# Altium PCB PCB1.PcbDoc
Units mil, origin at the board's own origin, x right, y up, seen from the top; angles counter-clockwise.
Board outline 6000 x 4000 mil, 2 copper layers (Top Layer, Bottom Layer); 112 components, 87 nets, 363 pads, 0 vias.
Unrouted connection lines stored in the file: 248.
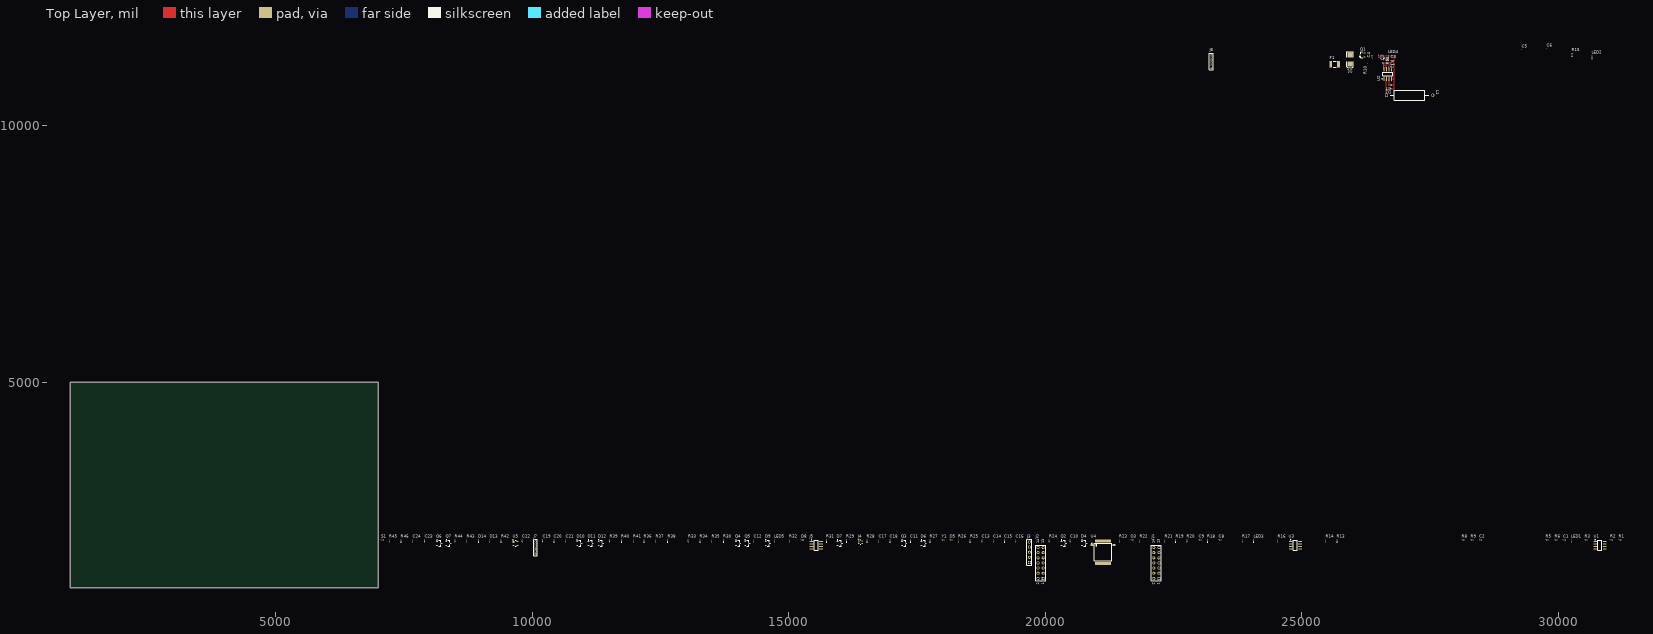
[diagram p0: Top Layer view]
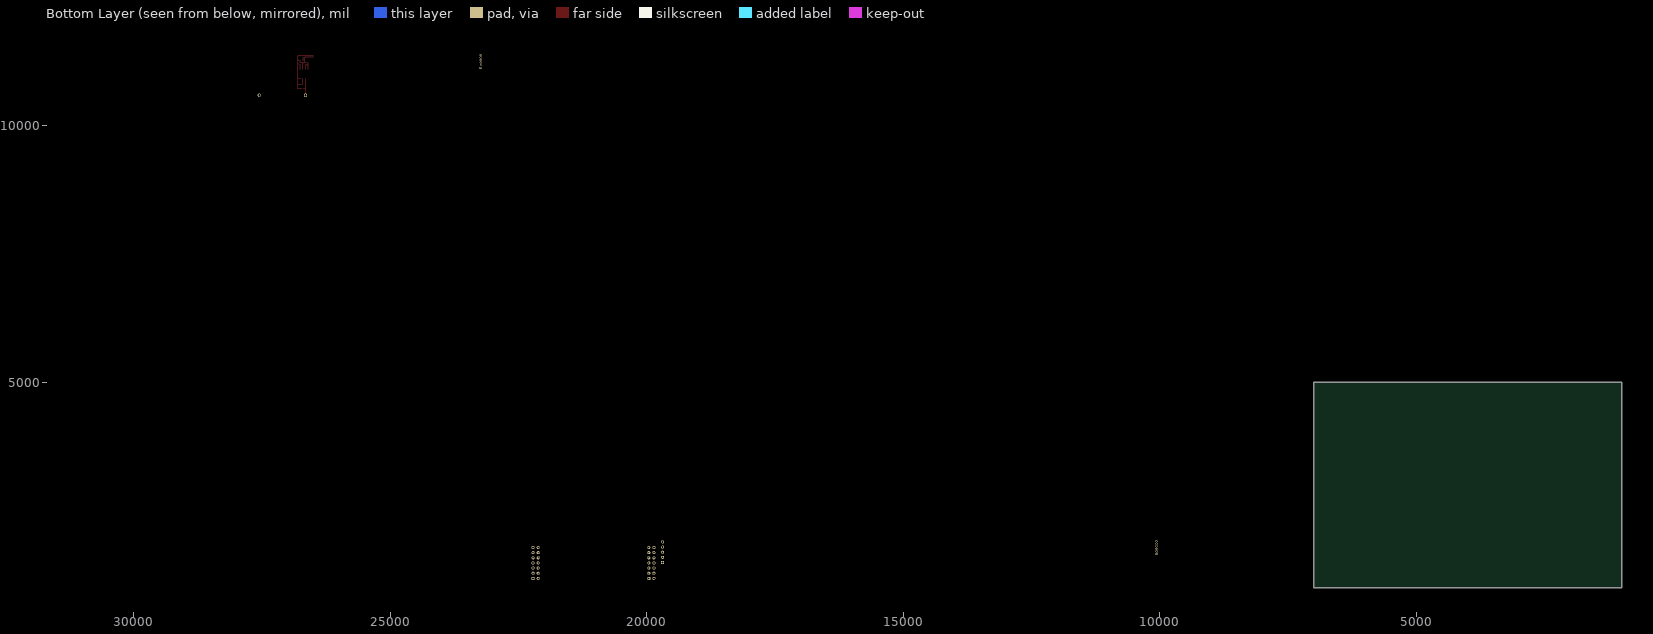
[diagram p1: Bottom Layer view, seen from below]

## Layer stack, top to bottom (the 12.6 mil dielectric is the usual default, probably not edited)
Top Solder: solder mask 0.4, Solder Resist, Dk 3.5
Top Layer: signal copper 1.4
Dielectric 1: dielectric 12.6, FR-4, Dk 4.8
Bottom Layer: signal copper 1.4
Bottom Solder: solder mask 0.4, Solder Resist, Dk 3.5

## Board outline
1000,1000 7000,1000 7000,5000 1000,5000

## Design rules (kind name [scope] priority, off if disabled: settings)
Clearance [All] p1: gap=10 ignorepadtopadclearanceinfootprint=FALSE except(0: Arc-Hole Track-Hole SMDPad-Hole THPad-Hole Via-Hole Fill-Hole Poly-Hole Region-Hole Text-Hole)
PolygonConnect [All] p1: connectstyle=Relief reliefconductorwidth=10 reliefentries=4 polygonreliefangle="90 Angle" airgapwidth=10
RoutingVias [All] p1: holewidth=28 width=50 viastyle="Through Hole" minholewidth=28 minwidth=50 maxholewidth=28 maxwidth=50
SolderMaskExpansion [All] p1: expansion=4
Width [All] p1: maxlimit=10 minlimit=10 preferedwidth=10
30 further rules are at their usual default settings.

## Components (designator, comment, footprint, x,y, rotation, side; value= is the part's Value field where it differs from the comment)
C1 "100n" 0603 30125,1930 r0 top
C2 "4n7" 0603 28490,1930 r0 top value=100n
C3 "4n7" 0603 26500,11351.22 r270 top value=100n
C3 "100n" 0603 26765,11275 r0 top
C4 "10u/16" 0603 26370,11351.22 r90 top value=470u/16
C5 "100u/6V3" 0603 29318.78,11480 r0 top value=470u/16
C6 "100n" 0603 29803.78,11500 r0 top
C7 "100p" 0603 26715,10795 r180 top value=100pF
C8 "100n" 0603 23410,1930 r0 top
C9 "4n7" 0603 23020,1930 r0 top value=100n
C10 "100n" 0603 20485,1915 r90 top
C11 "100n" 0603 17375,1915 r90 top
C12 "100n" 0603 14320,1915 r90 top
C13 "100n" 0603 18765,1915 r90 top
C14 "100n" 0603 18985,1915 r90 top
C15 "100n" 0603 19205,1915 r90 top
C16 "100n" 0603 19425,1915 r90 top
C17 "27p" 0603 16755,1915 r90 top value=100n
C18 "27p" 0603 16975,1915 r90 top value=100n
C19 "100n" 0603 10205,1915 r90 top
C20 "100n" 0603 10425,1915 r90 top
C21 "100n" 0603 10655,1915 r90 top
C22 "100n" 0603 9805,1915 r90 top
C23 "100n" 0603 7905,1915 r90 top
C24 "10n" 0603 7675,1915 r90 top value=100pF
D1 "P6SMB15A" SMB 25940,11291.42 r270 top
D2 "LL5817" 0603 26710,10725 r180 top
D3 "LL4148" 0603 21700,1930 r0 top
D4 "BAT54S" SOT-23_L 20760,1860 r0 top
D5 "LL4148" 0603 18165,1930 r0 top
D6 "BAT54S" SOT-23_L 17630,1860 r0 top
D7 "BAT54S" SOT-23_L 15995,1860 r0 top
D8 "LL4148" 0603 15270,1930 r0 top
D9 "BAT54S" SOT-23_L 14595,1860 r0 top
D10 "BAT54S" SOT-23_L 10920,1860 r0 top
D11 "BAT54S" SOT-23_L 11140,1860 r0 top
D12 "BAT54S" SOT-23_L 11340,1860 r0 top
D13 "LL4148" 0603 9175,1915 r90 top
D14 "LL4448" 0603 8955,1915 r90 top
F1 "Fuse 1" 1812 25640,11200 r0 top
J1 "Header 7X2" HDR2X7 22215,1180 r90 top
J2 "Header 7X2" HDR2X7 19960,1180 r90 top
J3 "ZL201" HDR1X5 19690,1490 r90 top
J4 "MX-43045-0400" SOT-343_L 16400,1885 r0 top
J5 "MX-43045-0800" SO8_L 15535,1825 r0 top
J6 "MX-43045-0600" MHDR1X6 23235,11130 r90 top
J7 "MX-43045-0600" MHDR1x6 10065,1655 r90 top
L1 "DL22-330" AXIAL-0.9 27100,10595 r0 top value=100uH
LED1 "HCL-1904AYL" 0603 30250,1915 r90 top
LED2 "HCL-1903BG4" 0603 30655,11341.22 r90 top
LED3 "HCL-1906BR1" 0603 24060,1915 r90 top
LED4 "HCL-1904AYL" 0603 26690,11350 r90 top
LED5 "HCL-1906BR1" 0603 14720,1915 r90 top
Q1 "BSS138" SOT23_L 26180,11380 r180 top
Q2 "BSS123" SOT-23_L 20360,1860 r0 top
Q3 "BSS123" SOT-23_L 17250,1860 r0 top
Q4 "BSS123" SOT-23_L 14015,1860 r0 top
Q5 "BSS123" SOT-23_L 14195,1860 r0 top
Q6 "BSS123" SOT-23_L 8190,1860 r0 top
Q7 "BSS123" SOT-23_L 8370,1860 r0 top
R1 "CAN0001" 0603 31210,1930 r0 top
R2 "CAN0001" 0603 31040,1930 r0 top
R3 "nc" 0603 30545,1930 r0 top value=1K
R4 "1R" 0603 26613.78,11225 r0 top value=1K
R5 "4k7" 0603 29785,1930 r0 top value=1K
R6 "1k" 0603 29955,1930 r0 top value=1K
R8 "68" 0603 28150,1930 r0 top value=1K
R9 "68" 0603 28320,1930 r0 top value=1K
R10 "1M" 0603 26236.22,11210 r180 top value=1K
R11 "1k2 1%" 0603 26766.22,11195 r180 top value=1K
R12 "4k7" 0603 26675,11275 r0 top value=1K
R13 "CAN0001" 0603 25685,1915 r90 top
R14 "CAN0001" 0603 25465,1915 r90 top
R15 "1k8" 0603 30265,11395 r90 top value=1K
R16 "nc" 0603 24530,1915 r90 top value=1K
R17 "4k7" 0603 23840,1915 r90 top value=1K
R18 "1k" 0603 23160,1915 r90 top value=1K
R19 "68" 0603 22540,1915 r90 top value=1K
R20 "68" 0603 22760,1915 r90 top value=1K
R21 "10k" 0603 22330,1915 r90 top value=1K
R22 "10k" 0603 21840,1915 r90 top value=1K
R23 "1k" 0603 21440,1915 r90 top value=1K
R24 "4k7" 0603 20075,1915 r90 top value=1K
R25 "10k" 0603 18535,1915 r90 top value=1K
R26 "10k" 0603 18305,1915 r90 top value=1K
R27 "1k" 0603 17755,1915 r90 top value=1K
R28 "4k7" 0603 16525,1915 r90 top value=1K
R29 "10k" 0603 16125,1915 r90 top value=1K
R30 "1k8" 0603 13730,1915 r90 top value=1K
R31 "10k" 0603 15735,1915 r90 top value=1K
R32 "1k" 0603 15010,1915 r90 top value=1K
R33 "nc" 0603 13040,1915 r90 top value=1K
R34 "4k7" 0603 13270,1915 r90 top value=1K
R35 "4k7" 0603 13500,1915 r90 top value=1K
R36 "10k" 0603 12180,1915 r90 top value=1K
R37 "10k" 0603 12410,1915 r90 top value=1K
R38 "10k" 0603 12640,1915 r90 top value=1K
R39 "470" 0603 11510,1915 r90 top value=1K
R40 "1k" 0603 11740,1915 r90 top value=1K
R41 "1k" 0603 11970,1915 r90 top value=1K
R42 "4k7" 0603 9395,1915 r90 top value=1K
R43 "10k" 0603 8725,1915 r90 top value=1K
R44 "4k7" 0603 8495,1915 r90 top value=1K
R45 "4k7" 0603 7215,1915 r90 top value=1K
R46 "4k7" 0603 7445,1915 r90 top value=1K
S1 "DTSM32NB" 0603 7090,1930 r0 top
U1 "MCP2551-I/SN" so8_L 30810,1825 r0 top
U2 "MC33063AD" SO8_N 26675,11010 r90 top
U3 "MCP2551-I/SN" SO8_L 24875,1825 r0 top
U4 "DSPIC30F5011-30I/PT" TQFP-PT64_L 21125,1690 r0 top
U5 "MCP1320-46LT" SOT-143_L 9680,1860 r0 top
Y1 "10MHz" 0603 18015,1930 r0 top

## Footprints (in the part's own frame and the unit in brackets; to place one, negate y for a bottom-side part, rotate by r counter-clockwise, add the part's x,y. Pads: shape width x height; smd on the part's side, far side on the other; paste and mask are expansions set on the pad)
0603 [mm] "Chip Inductor, Body 0.6x0.3mm, IPC High Density"
  rect 0.5x0.3 smd: 1(-0.35,0) 2(0.35,0)
  silkscreen extent -0.9,-0.05 -0.9,0.05, body extent -0.33,-0.18 0.33,0.18, height 0.55
1812 [mm] "Chip Capacitor, Body 4.5x3.2mm, IPC High Density"
  rect 1.4x3.3 smd: 1(-1.9,0) 2(1.9,0)
  silkscreen extent -0.8,-1.55 0.8,1.55, body extent -2.4,-1.7 2.4,1.7, height 1.4
AXIAL-0.9 [mm] "Axial Device, Thru-Hole; 2 Leads; 0.9 in Pin Spacing"
  round 1.65 hole 1: 1(-11.43,0) 2(11.43,0)
  silkscreen extent -9.53,-2.54 9.53,2.54
HDR1X5 [mm] "Connector; Header; 5 Position"
  rect 1.5x1.5 hole 0.9: 1(0,0)
  round 1.5 hole 0.9: 2(2.54,0) 3(5.08,0) 4(7.62,0) 5(10.16,0)
  silkscreen extent -1.27,-1.27 11.43,1.27
HDR2X7 [mm] "Connector; Header; 7x2 Position"
  rect 1.5x1.5 hole 0.9: 1(0,0)
  round 1.5 hole 0.9: 2(0,2.54) 3(2.54,0) 4(2.54,2.54) 5(5.08,0) 6(5.08,2.54) 7(7.62,0) 8(7.62,2.54) 9(10.16,0) 10(10.16,2.54) 11(12.7,0) 12(12.7,2.54) 13(15.24,0) 14(15.24,2.54)
  silkscreen extent -1.27,-1.27 16.51,3.81
MHDR1X6 [mm] "Connector; Header; 6 Position"
  rect 1x1 hole 0.6: 1(0,0)
  round 1 hole 0.6: 2(1.27,0) 3(2.54,0) 4(3.81,0) 5(5.08,0) 6(6.35,0)
  silkscreen extent -0.9,-0.9 7.25,0.9
MHDR1x6 [mm] "Connector; Header; 6 Position"
  rect 1x1 hole 0.6: 1(0,0)
  round 1 hole 0.6: 2(1.27,0) 3(2.54,0) 4(3.81,0) 5(5.08,0) 6(6.35,0)
  silkscreen extent -0.9,-0.9 7.25,0.9
SMB [mm] "DO-214-AA/SMB; 2 C-Bend Leads; Body 5.3 x 3.6 mm, inc. leads (LxW)"
  rect 2.3x2.3 smd: 1(-2.25,0) 2(2.25,0)
  silkscreen extent -3.8,-1.55 4.1,1.55
SO8_L [mm] "SOIC, 8-Leads, Body 4.9x3.9mm, Pitch 1.27mm, IPC High Density"
  oval 1.9x0.6 smd: 1(-2.35,1.905) 2(-2.35,0.635) 3(-2.35,-0.635) 4(-2.35,-1.905) 5(2.35,-1.905) 6(2.35,-0.635) 7(2.35,0.635) 8(2.35,1.905)
  silkscreen extent -2.47,-2.5 1,2.88, body extent -2,-2.5 2,2.5, height 1.75
so8_L [mm] "SOIC, 8-Leads, Body 4.9x3.9mm, Pitch 1.27mm, IPC High Density"
  oval 1.9x0.6 smd: 1(-2.35,1.905) 2(-2.35,0.635) 3(-2.35,-0.635) 4(-2.35,-1.905) 5(2.35,-1.905) 6(2.35,-0.635) 7(2.35,0.635) 8(2.35,1.905)
  silkscreen extent -2.47,-2.5 1,2.88, body extent -2,-2.5 2,2.5, height 1.75
SO8_N [mm] "SOIC, 8-Leads, Body 4.9x3.9mm, Pitch 1.27mm, IPC Medium Density"
  oval 2.2x0.6 smd: 1(-2.4,1.905) 2(-2.4,0.635) 3(-2.4,-0.635) 4(-2.4,-1.905) 5(2.4,-1.905) 6(2.4,-0.635) 7(2.4,0.635) 8(2.4,1.905)
  silkscreen extent -2.52,-2.5 0.9,2.88, body extent -2,-2.5 2,2.5, height 1.75
SOT23_L [mm] "SOT23, 3-Leads, Body 2.9x1.3mm, Pitch 0.95mm, Lead Span 2.3mm - Reverse Pinning, IPC High Density"
  rect 0.85x0.6 smd: 1(1.075,0) 2(-1.075,-0.95) 3(-1.075,0.95)
  silkscreen extent -0.3,-1.5 1.47,1.5, body extent -0.7,-1.5 0.7,1.5, height 1.1
SOT-23_L [mm] "SOT23, 3-Leads, Body 2.9x1.3mm, Pitch 0.95mm, Lead Span 2.5mm, IPC High Density"
  rect 0.85x0.6 smd: 1(-1.075,0.95) 2(-1.075,-0.95) 3(1.075,0)
  silkscreen extent -1.2,-1.5 0.7,1.92, body extent -0.7,-1.5 0.7,1.5, height 1.1
SOT-143_L [mm] "SOT143, 4-Leads, Body 2.9x1.3mm, Pitch 1.9mm, Lead Span 2.5mm, IPC High Density"
  rect 1x1 smd: 1(-1,0.75)
  rect 1x0.6 smd: 2(-1,-0.95) 3(1,-0.95) 4(1,0.95)
  silkscreen extent -1.47,-1.5 0.3,1.92, body extent -0.7,-1.52 0.7,1.52, height 1.1
SOT-343_L [mm] "SOT343, 4-Leads, Body 2x1.3 mm, Pitch 1.3mm, Lead Span 2.1mm, IPC High Density"
  rect 0.85x0.5 smd: 1(-0.875,0.65) 3(0.875,-0.65) 4(0.875,0.65)
  rect 0.85x0.8 smd: 2(-0.875,-0.5)
  silkscreen extent -0.92,-1.1 0.2,1.35, body extent -0.7,-1.1 0.7,1.1, height 1
TQFP-PT64_L [mm] "Thin QFP, 64-Leads, Body 10x10mm, Pitch 0.5mm, IPC High Density"
  oval 1.55x0.25 smd: 1(-5.525,3.75) 2(-5.525,3.25) 3(-5.525,2.75) 4(-5.525,2.25) 5(-5.525,1.75) 6(-5.525,1.25) 7(-5.525,0.75) 8(-5.525,0.25) 9(-5.525,-0.25) 10(-5.525,-0.75) 11(-5.525,-1.25) 12(-5.525,-1.75) 13(-5.525,-2.25) 14(-5.525,-2.75) 15(-5.525,-3.25) 16(-5.525,-3.75) 33(5.525,-3.75) 34(5.525,-3.25) 35(5.525,-2.75) 36(5.525,-2.25) 37(5.525,-1.75) 38(5.525,-1.25) 39(5.525,-0.75) 40(5.525,-0.25) 41(5.525,0.25) 42(5.525,0.75) 43(5.525,1.25) 44(5.525,1.75) 45(5.525,2.25) 46(5.525,2.75) 47(5.525,3.25) 48(5.525,3.75)
  oval 0.25x1.55 smd: 17(-3.75,-5.525) 18(-3.25,-5.525) 19(-2.75,-5.525) 20(-2.25,-5.525) 21(-1.75,-5.525) 22(-1.25,-5.525) 23(-0.75,-5.525) 24(-0.25,-5.525) 25(0.25,-5.525) 26(0.75,-5.525) 27(1.25,-5.525) 28(1.75,-5.525) 29(2.25,-5.525) 30(2.75,-5.525) 31(3.25,-5.525) 32(3.75,-5.525) 49(3.75,5.525) 50(3.25,5.525) 51(2.75,5.525) 52(2.25,5.525) 53(1.75,5.525) 54(1.25,5.525) 55(0.75,5.525) 56(0.25,5.525) 57(-0.25,5.525) 58(-0.75,5.525) 59(-1.25,5.525) 60(-1.75,5.525) 61(-2.25,5.525) 62(-2.75,5.525) 63(-3.25,5.525) 64(-3.75,5.525)
  silkscreen extent -5.65,-4.35 4.35,4.55, body extent -5,-5 5,5, height 1.6

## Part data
C1 C2 C3 C3 C6 C7 C8 C9 C10 C11 C12 C13 C14 C15 C16 C17 C18 C19 C20 C21 C22 C23 C24: library part Cap, "Capacitor"
C4 C5: library part "Cap Pol1", "Polarized Capacitor (Radial)"
D1: library part "D Zener", "Zener Diode"
D2 D3 D5 D8 D13: library part 1N4148, "High Conductance Fast Diode"
D4 D6 D7 D9 D10 D11 D12: "Schottky Barrier Double Diode"
D14: library part Diode, "Default Diode", PackageDocument=Sep-1996
F1: "Fuse"
J1 J2: "Header, 7-Pin, Dual row"
J3: library part CON5, "Connector"
J4: library part "Header 2X2", "Header, 2-Pin, Dual row"
J5: library part "Header 4X2A", "Header, 4-Pin, Dual row"
J6 J7: library part "Header 6", "Header, 6-Pin"
L1: library part "Inductor Iron", "Magnetic-Core Inductor"
LED1 LED2 LED3 LED4 LED5: library part LED3, "Typical BLUE SiC LED"
Q1: "N-Channel Enhancement Mode Vertical DMOS FET"
Q2 Q3 Q4 Q5 Q6 Q7: "N-channel Enhancement Mode Vertical D-MOSFET"
R1 R2 R13 R14: library part "Res Varistor", "Varistor (Voltage-Sensitive Resistor)"
R3 R4 R5 R6 R8 R9 R10 R11 R12 R15 R16 R17 R18 R19 R20 R21 R22 R23 R24 R25 R26 R27 R28 R29 R30 R31 R32 R33 R34 R35 R36 R37 R38 R39 R40 R41 R42 R43 R44 R45 R46: library part Res2, "Resistor"
S1: library part PUSHB, "Switch PushButton"
U1 U3: "High Speed CAN Transceiver, 8-Pin Plastic SOIC, Industrial Grade"
U2: "DC-to-DC Converter Control Circuit"
U4: library part CMP-0044-00148-1, "High-Performance 16-bit Digital Signal Controller, 66 KB Flash, 4 KB SRAM, 1 KB EEPROM, 64-Pin TQFP, Industrial Temperature"
U5: library part MCP1320
Y1: library part XTAL, "Crystal Oscillator"

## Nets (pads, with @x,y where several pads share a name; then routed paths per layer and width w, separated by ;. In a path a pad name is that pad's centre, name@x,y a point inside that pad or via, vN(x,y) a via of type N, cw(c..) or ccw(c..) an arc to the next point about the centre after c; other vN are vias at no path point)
+5V: C1.1 C5.1 C6.1 C8.1 C13.1 C14.1 C15.1 C16.1 C22.1 D4.2 D6.2 D7.2 D9.2 D10.2 D11.2 D12.2 D13.2 D14.2 J1.2 J2.2 J2.4 J2.6 J3.2 J4.2 L1.2 LED1.1 LED2.1 LED3.1 LED5.1 R22.1 R26.1 R31.1 R36.1 R37.1 R38.1 R42.1 R43.2 U1.3 U3.3 U4.10 U4.19 U4.26 U4.38 U4.57
+12V: C3.1@26751.22,11275 C3.2@26500,11337.44 C4.1 D1.2 F1.2 J5.5 R4.2 R10.1 R12.1 U2.6 | length 562.3
  Top Layer w10: C3.2@26500,11337.44 26654.99,11337.44 26661.22,11331.21 R12.1 26660.85,11274.63 26660.85,11225 ; R4.2 26660.85,11225 ; U2.6 26700,11219.14 26694.14,11225 ; C3.1@26751.22,11275 26750.91,11275 26750,11274.09 26751.22,11274.09 26751.22,11235.86 26740.36,11225 26694.14,11225 ; 26660.85,11225 26694.14,11225
+12VPWR: F1.1 J6.3 J7.3
ADC0: J1.4 U4.16
ADC1: J1.6 U4.15
ADC2: J1.8 U4.14
ADC3: J1.10 U4.13
ADC4: J1.12 U4.12
ButD: C10.1 D4.3 R22.2 R23.2 U4.23
ButD_IN: J5.2 R23.1
ButN: C11.1 D6.3 R26.2 R27.2 U4.22
ButN_IN: J5.3 R27.1
ButR: C12.1 D9.3 R31.2 R32.2 U4.21
ButR_IN: J5.4 R32.1
CAN_BMS_RX: U3.4 U4.58
CAN_BMS_TX: R17.2 U3.1 U4.59
CAN_BMSS_H: J7.1 R13.2 R20.1 U3.7
CAN_BMSS_L: J7.2 R14.1 R19.1 U3.6
CAN_MUX_RX: U1.4 U4.61
CAN_MUX_TX: R5.2 U1.1 U4.60
CAN_MUXED_H: J6.1 R1.2 R9.1 U1.7
CAN_MUXED_L: J6.2 R2.1 R8.1 U1.6
ChrgLED: Q6.3 R45.1 U4.29
ChrgLED_OUT: J7.6 Q6.1
FluidHeater: Q7.3 R46.1 U4.30
FluidHeater_OUT: J6.6 Q7.1
GND: C1.2 C2.1 C3.1@26500,11365 C3.2@26778.78,11275 C4.2 C5.2 C6.2 C7.1 C8.2 C9.1 C10.2 C11.2 C12.2 C13.2 C14.2 C15.2 C16.2 C17.2 C18.2 C19.2 C20.2 C21.2 C22.2 C23.1 C24.1 D2.1 D4.1 D6.1 D7.1 D9.1 D10.1 D11.1 D12.1 J1.14 J2.12 J2.14 J3.3 J4.1 J5.1 LED4.2 Q1.2 Q2.2 Q3.2 Q4.2 Q5.2 Q6.2 Q7.2 R1.1 R2.2 R6.2 R11.1 R13.1 R14.2 R15.2 R18.2 R24.2 R28.2 R34.2 R35.2 R45.2 R46.2 S1.1 U1.2 U2.4 U3.2 U4.9 U4.20 U4.25 U4.41 U4.56 U5.2 | length 1208.6
  Top Layer w10: C3.1@26500,11365 26500.61,11364.39 26689.39,11364.39 LED4.2 26799.14,11363.78 26805,11357.92 26805,11269.14 ; D2.1 26799.14,10725 26805,10730.86 26805,10800.86 ; C7.1 26799.14,10795 26805,10800.86 ; U2.4 26750.51,10915 26799.14,10915 26805,10920.86 ; C3.2@26778.78,11275 26799.14,11275 26805,11269.14 ; R11.1 26805,11195 ; 26805,10800.86 26805,10920.86 ; 26805,10920.86 26805,11195 ; 26805,11195 26805,11269.14
GPIOC13: J2.3 U4.47
GPIOC14: J2.1 U4.48
GPIOD0: J2.5 U4.46
GPIOD1: J1.13 U4.49
GPIOD2: J1.11 U4.50
GPIOD3: J1.9 U4.51
GPIOD4: J1.7 U4.52
GPIOD5: J1.5 U4.53
GPIOD6: J1.3 U4.54
GPIOD7: J1.1 U4.55
GPIOD8: J2.13 U4.42
GPIOD9: J2.11 U4.43
GPIOD10: J2.9 U4.44
GPIOD11: J2.7 U4.45
GROUND: D1.1 J6.4 J7.4 Q1.1
ILUM: D7.3 J4.4 Q4.3 R34.1
IMP: C19.1 D10.3 R36.2 R39.2 U4.11
IMP_IN: J4.3 R39.1
IsFHerror: C21.1 D12.3 R38.2 R41.2 U4.32
IsFHerror_IN: J6.5 R41.1
IsHeating: C20.1 D11.3 R37.2 R40.2 U4.31
IsHeating_IN: J7.5 R40.1
LightD: Q2.3 R24.1 U4.24
LightD_OUT: D3.1 J5.6 Q2.1
LightN: Q3.3 R28.1 U4.27
LightN_OUT: D5.1 J5.7 Q3.1
LightR: Q5.3 R35.1 U4.28
LightR_OUT: D8.1 J5.8 Q5.1
MCLR: J3.1 R44.1 U4.7
NetC2_2: C2.2 R3.2 R8.2 R9.2
NetC7_2: C7.2 U2.3 | length 121
  Top Layer w10: U2.3 26700.61,10914.9 26700.61,10795.61 C7.2
NetC9_2: C9.2 R16.2 R19.2 R20.2
NetC24_2: C24.2 D14.1 R43.1 S1.2 U5.3
NetD2_2: D2.2 L1.1 U2.2 | length 366.7
  Top Layer w10: L1.1 26650,10725 ; U2.2 26650,10725 ; D2.2 26650,10725
NetD3_2: D3.2 R21.2
NetD5_2: D5.2 R25.2
NetD8_2: D8.2 R29.2
NetLED1_2: LED1.2 R5.1
NetLED2_2: LED2.2 R15.1
NetLED3_2: LED3.2 R17.1
NetLED4_1: LED4.1 R12.2 | length 61.7
  Top Layer w10: R12.2 26689.39,11275.61 26689.39,11335.61 LED4.1
NetLED5_2: LED5.2 R30.2
NetQ1_3: Q1.3 R10.2
NetQ4_1: Q4.1 R21.1 R25.1 R29.1
NetR3_1: R3.1 U1.5
NetR4_1: R4.1 U2.1 U2.7 U2.8 | length 249.7
  Top Layer w10: U2.8 26600,11190 ; R4.1 26600,11190 ; U2.7 26650,11179.14 26644.14,11185 26605,11185 26600,11190
NetR6_1: R6.1 U1.8
NetR7_2: R11.2 U2.5 | length 91.7
  Top Layer w10: U2.5 26751.22,11105.71 26751.22,11194.09 26752.13,11195 R11.2
NetR16_1: R16.1 U3.5
NetR18_1: R18.1 U3.8
NetR30_1: R30.1 U4.37
NetR33_1: R33.1 U4.8
OSC1: C17.1 U4.39 Y1.2
OSC2: C18.1 U4.40 Y1.1
PGC: J3.5 U4.17
PGD: J3.4 U4.18
RESET: C23.2 D13.1 R42.2 R44.2 U5.1
RX: J2.10 U4.34
TX: J2.8 U4.33
WDI: R33.2 U5.4
pads on no net: U4.1 U4.2 U4.3 U4.4 U4.5 U4.6 U4.35 U4.36 U4.62 U4.63 U4.64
